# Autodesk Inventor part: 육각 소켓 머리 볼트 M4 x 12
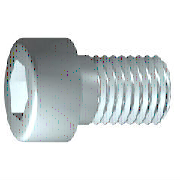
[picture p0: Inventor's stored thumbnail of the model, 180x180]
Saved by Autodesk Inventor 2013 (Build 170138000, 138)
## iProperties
IsCustomPart: 1
Created: 2012-02
Part Number: 육각 소켓 머리 볼트 M4 x 12
Material: 강철, 연강
Description: 6각 소켓 머리 캡 나사
Document SubType Name: Modeling
Standard: ISO 4762
Designer: mdu-01
Standard Revision: Fourth edition 2004-03-01
Standards Organization: ISO
Language: ko-KR
Size Designation: M4 x 12
Categories: <MemberInstance><Categories><Category DisplayName="조임쇠" InternalName="e4da775c-781d-43d5-af7c-5136215cf5a6" Mnemonic="FSTN"><Category DisplayName="볼트" InternalN
Density: 7.75 g/cm^3
Author: mdu-01
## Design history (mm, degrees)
sketch "스케치1"
  geometry: L1 (-1, 0)-(12, 0); L2 (12, 0)-(12, 2); L3 (12, 2)-(1.75, 2); L4 (1.75, 2)-(1.32, 2); L5 (1.32, 2)-(0, 2); L6 (0, 2)-(0, 3.5); L7 (0, 3.5)-(-4, 3.5); L8 (-4, 3.5)-(-4, 1.732); L9 (-4, 1.732)-(-2, 1.732); L10 (-2, 1.732)-(-1, 0); L11 (-7.2, 0)-(15.2, 0) reference; L12 (0, -0.7)-(0, 4.2) reference; L13 (1.75, 2)-(0, 2)
  constraints: 22 end point, 6 parallel, 2 collinear, 2 perpendicular, 1 horizontal, 1 point on line
  dimensions: "d1" = 10.25 distance from line of L3.end L2 (= GEL); "d2" = 0.42952 distance of L4.end L3.end (computed from GAL); "d3" = 4 distance between parallel lines of L8 L6 (= KOH); "d4" = 2 distance of L8.end L9.end (= INTI); "d5" = 60 deg angle of L10 L1; "d6" = 4 diameter of L3 L1 (= GD); "d7" = 4 diameter of L5 L1 (= BDM); "d8" = 3.4641 diameter of L9 L1 (= 1.1547 x SW); "d9" = 7 diameter of L7 L1 (= KOD); "d26" = 12 distance between parallel lines of L12 L2 (= NLG)
revolve "본체" sketch "스케치1" stored, may be unused: angle "d10" = 90 deg
sketch "스케치2"
  geometry: L1 (0, -4.9)-(0, 4.9) reference; L2 (-4.9, 0)-(4.9, 0) reference; L3 (1.732, 0)-(0.866, -1.5); L4 (0.866, -1.5)-(-0.866, -1.5); L5 (-0.866, -1.5)-(-1.732, 0); L6 (-1.732, 0)-(-0.866, 1.5); L7 (-0.866, 1.5)-(0.866, 1.5); L8 (0.866, 1.5)-(1.732, 0); 2 further points
  constraints: 12 end point, 1 coincident, 1 horizontal alignment, 1 point on line, 12 other
extrude "슬롯" join sketch "스케치2" stored distance "d11" = 10; taper "d12" = 0 deg
workplane "Work Plane1"
fillet "Fillet2" dims "d30" = 0.1 (= R)
body "Solid1"
fillet "모깎기1" dims "d17" = 0.4 (= RR)
feature "스레드" dims "d13" = 10.25 (= GEL), "d14" = 0
chamfer "모따기1" distance "d15" = 0.42941 (= -0.5 x SPD + 0.5 x GD); stored, may be unused: second distance "d16" = 0.42941 (= GUL), angle "d27" = 45 deg
other parameters: "GD" = 4 [user parameter; used in 2 equation terms], "NLG" = 12 [user parameter; used in 1 equation term], "GEL" = 10.25 [user parameter; used in 2 equation terms], "KOD" = 7 [user parameter; used in 1 equation term], "KOH" = 4 [user parameter; used in 1 equation term], "INTI" = 2 [user parameter; used in 1 equation term], "GAL" = 0.42941 (= 0.61345 x PTC) [user parameter; used in 1 equation term], "GUL" = 0.42941 (= 0.61345 x PTC) [user parameter; used in 1 equation term], "BDM" = 4 (= NND) [user parameter; used in 1 equation term], "SW" = 3 [user parameter; used in 2 equation terms], "RR" = 0.4 [user parameter; used in 1 equation term], "SPD" = 3.14117 (= NND - 1.2269 x PTC) [user parameter; used in 1 equation term], "d19" = 0, "d28" = 0, "d29" = 0, "R" = 0.1 [user parameter; used in 1 equation term], "TOA" = 30 deg [user parameter], "GD1" = 3.14117 (= THREADDIA - 1.2269 x PTC) [user parameter], "THREADDIA" = 4 [user parameter; used in 1 equation term], "FAWI" = 45 deg [user parameter], "TPU" = 14.28571 (computed from PTC) [user parameter], "PTC" = 0.7 [user parameter; used in 5 equation terms], "NND" = 4 [user parameter; used in 2 equation terms], "E0" = 3.465 (= 1.155 x SW) [user parameter]
